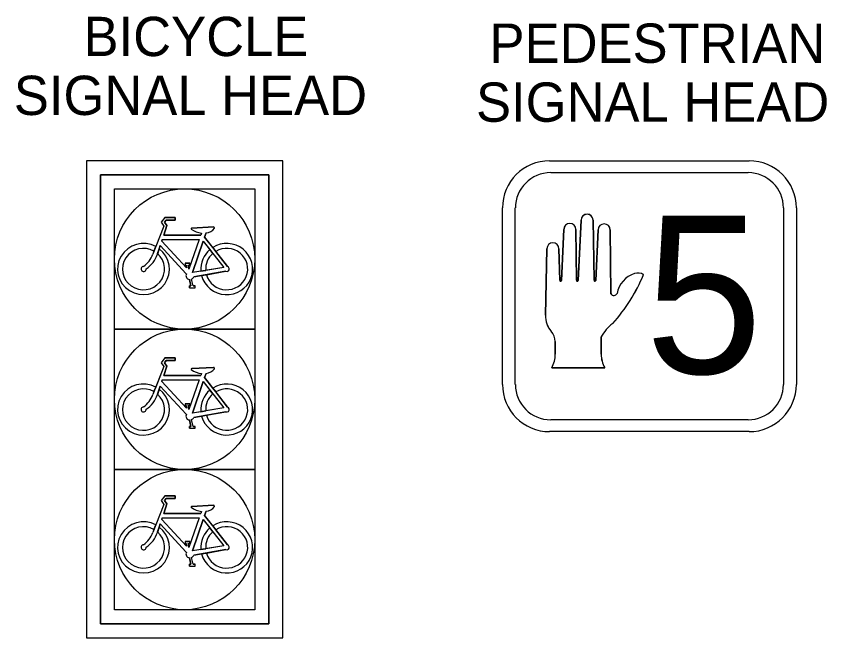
# Model space of a CAD drawing. Extents: x -30.3 to 21.6, y 6.6 to 27.2.
# Drawn here: x 18.672 to 21.56, y 9.341 to 11.556 of the extents above; entities that cross this region are included whole.
import ezdxf

# ---------------------------------------------------------------- set-up
doc = ezdxf.new("R2010")
doc.units = 0
for name, color, linetype in [('Default', 7, 'Continuous'), ('UT_X_Water', 7, 'Continuous'), ('VG_X_Cells', 7, 'Continuous')]:
    doc.layers.add(name, color=color, linetype=linetype)

# ---------------------------------------------------------------- blocks, each defined once
blk = doc.blocks.new('HAND')
at = {"layer": 'Default'}
for points in [[(0.00046, 0.10474), (0.00044, 0.10454), (0.00404, 0.17759), (0.00405, 0.17759)], [(0.01857, 0.17759), (0.01856, 0.17759), (0.01992, 0.10497), (0.01992, 0.10496)], [(-0.01964, 0.10473), (-0.01966, 0.10454), (-0.0167, 0.16646), (-0.0167, 0.16646)], [(-0.00218, 0.16646), (-0.0022, 0.16646), (-0.0014, 0.10497), (-0.0014, 0.10497)], [(0.02178, 0.10473), (0.02176, 0.10454), (0.0247, 0.16586), (0.0247, 0.16586)], [(0.03922, 0.16586), (0.03922, 0.16586), (0.04024, 0.08875), (0.04024, 0.08875)], [(-0.03873, 0.06259), (-0.03874, 0.06259), (-0.03723, 0.143), (-0.03723, 0.143)], [(-0.02271, 0.143), (-0.02273, 0.143), (-0.0215, 0.10497), (-0.0215, 0.10497)], [(0.04768, 0.08902), (0.04767, 0.08901)], [(-0.03203, 0.04323), (-0.03205, 0.04321)], [(-0.02709, 0.01543), (-0.02709, 0.01543), (-0.02709, 0.03084), (-0.02709, 0.03084)], [(0.02843, 0.03645), (0.02843, 0.03645), (0.02843, 0.01543), (0.02843, 0.01543)], [(0.03266, -0.00083), (-0.03133, -0.00083), (-0.03132, -0.00082)], [(0.03266, -0.00082), (0.03266, -0.00083)]]:
    blk.add_lwpolyline(points, dxfattribs=at)
for centre, radius, start, end in [((0.01131, 0.17759), 0.00726, 0, 180), ((-0.00944, 0.16646), 0.00726, 0, 180), ((0.03196, 0.16586), 0.00726, 0, 180), ((-0.02997, 0.143), 0.00726, 0, 180), ((-0.11405, 0.19246), 0.20979, 318.20581, 337.37116), ((0.07799, 0.0836), 0.0308, 107.24664, 169.88264), ((0.07298, 0.10185), 0.01189, 56.22904, 110.27261), ((-0.02058, 0.10476), 0.000943, 167.14009, 358.60988), ((-0.00048, 0.10476), 0.000943, 167.14009, 358.60988), ((0.02084, 0.10475), 0.000943, 167.14009, 358.60988), ((0.0439, 0.0907), 0.00414, 208.07031, 335.99597), ((-0.01095, 0.06133), 0.02781, 177.39642, 220.65739), ((0.07421, 0.01116), 0.05231, 127.51943, 151.0809), ((-0.04757, 0.02985), 0.02051, 2.77491, 40.72121), ((-0.0593, 0.01514), 0.03221, 330.28872, 0.51813), ((0.06064, 0.01514), 0.03221, 179.48187, 209.71128)]:
    blk.add_arc(centre, radius, start, end, dxfattribs=at)

msp = doc.modelspace()

# ---------------------------------------------------------------- linework, layer by layer
at = {"layer": 'VG_X_Cells'}
for p, q in [((20.5725, 11.041), (21.2834, 11.041)), ((20.5761, 10.9988), (21.2798, 10.9988)), ((20.4043, 10.2439), (20.4043, 10.8728)), ((20.4501, 10.2439), (20.4501, 10.8728)), ((21.4058, 10.8728), (21.4058, 10.2439)), ((21.4516, 10.8728), (21.4516, 10.2439)), ((19.2013, 10.8391), (19.1883, 10.8221)), ((19.2013, 10.8391), (19.2386, 10.8391)), ((19.2386, 10.8391), (19.2386, 10.8297)), ((19.1978, 10.8083), (19.1583, 10.7084)), ((19.1883, 10.8221), (19.1978, 10.8083)), ((19.2083, 10.8098), (19.1971, 10.776)), ((19.2061, 10.8297), (19.2001, 10.8218)), ((19.2001, 10.8218), (19.2083, 10.8098)), ((19.2386, 10.8297), (19.2061, 10.8297)), ((19.2061, 10.8297), (19.2061, 10.8297)), ((19.2971, 10.801), (19.3752, 10.8051)), ((19.1971, 10.776), (19.3291, 10.776)), ((19.3317, 10.7835), (19.3291, 10.776)), ((19.3483, 10.7842), (19.343, 10.7687)), ((19.192, 10.7606), (19.19, 10.7548)), ((19.19, 10.7548), (19.2782, 10.6595)), ((19.192, 10.7606), (19.3236, 10.7606)), ((19.3236, 10.7606), (19.2864, 10.6552)), ((19.3382, 10.7547), (19.2999, 10.6427)), ((19.3382, 10.7547), (19.4115, 10.6606)), ((19.343, 10.7687), (19.4246, 10.6639)), ((19.1848, 10.739), (19.1746, 10.7084)), ((19.1848, 10.739), (19.2778, 10.6383)), ((19.2734, 10.6759), (19.2897, 10.6759)), ((19.2734, 10.6759), (19.2734, 10.669)), ((19.2734, 10.669), (19.2769, 10.669)), ((19.2769, 10.669), (19.2782, 10.6595)), ((19.2846, 10.669), (19.2864, 10.6552)), ((19.2846, 10.669), (19.2897, 10.669)), ((19.2897, 10.6759), (19.2897, 10.669)), ((19.4115, 10.6606), (19.2999, 10.6427)), ((19.4188, 10.6471), (19.3041, 10.6271)), ((19.2943, 10.595), (19.2889, 10.6179)), ((19.3024, 10.595), (19.2968, 10.6192)), ((19.2891, 10.5881), (19.2891, 10.595)), ((19.2891, 10.595), (19.2943, 10.595)), ((19.2891, 10.5881), (19.3091, 10.5881)), ((19.3024, 10.595), (19.3091, 10.595)), ((19.3091, 10.5881), (19.3091, 10.595)), ((19.2013, 10.3385), (19.1883, 10.3214)), ((19.1883, 10.3214), (19.1978, 10.3076)), ((19.2061, 10.329), (19.2001, 10.3211)), ((19.2001, 10.3211), (19.2083, 10.3091)), ((19.2013, 10.3385), (19.2386, 10.3385)), ((19.2386, 10.329), (19.2061, 10.329)), ((19.2061, 10.329), (19.2061, 10.329)), ((19.2386, 10.3385), (19.2386, 10.329)), ((19.1978, 10.3076), (19.1583, 10.2077)), ((19.2083, 10.3091), (19.1971, 10.2754)), ((19.2971, 10.3004), (19.3752, 10.3045)), ((19.3317, 10.2829), (19.3291, 10.2754)), ((19.3483, 10.2835), (19.343, 10.2681)), ((19.192, 10.26), (19.19, 10.2542)), ((19.19, 10.2542), (19.2782, 10.1588)), ((19.192, 10.26), (19.3236, 10.26)), ((19.1971, 10.2754), (19.3291, 10.2754)), ((19.3236, 10.26), (19.2864, 10.1546)), ((19.3382, 10.254), (19.2999, 10.1421)), ((19.3382, 10.254), (19.4115, 10.16)), ((19.343, 10.2681), (19.4246, 10.1633)), ((19.1848, 10.2383), (19.1746, 10.2077)), ((19.1848, 10.2383), (19.2778, 10.1376)), ((19.2734, 10.1752), (19.2897, 10.1752)), ((19.2734, 10.1752), (19.2734, 10.1684)), ((19.2734, 10.1684), (19.2769, 10.1684)), ((19.2769, 10.1684), (19.2782, 10.1588)), ((19.2846, 10.1684), (19.2864, 10.1546)), ((19.2846, 10.1684), (19.2897, 10.1684)), ((19.2897, 10.1752), (19.2897, 10.1684)), ((19.4115, 10.16), (19.2999, 10.1421)), ((19.4188, 10.1464), (19.3041, 10.1265)), ((19.2943, 10.0943), (19.2889, 10.1173)), ((19.3024, 10.0943), (19.2968, 10.1185)), ((21.2798, 10.118), (20.5761, 10.118)), ((19.2891, 10.0875), (19.2891, 10.0943)), ((19.2891, 10.0943), (19.2943, 10.0943)), ((19.2891, 10.0875), (19.3091, 10.0875)), ((19.3024, 10.0943), (19.3091, 10.0943)), ((19.3091, 10.0875), (19.3091, 10.0943)), ((21.2834, 10.0757), (20.5725, 10.0757)), ((19.2013, 9.8472), (19.1883, 9.8302)), ((19.1883, 9.8302), (19.1978, 9.8163)), ((19.2061, 9.8377), (19.2001, 9.8298)), ((19.2001, 9.8298), (19.2083, 9.8179)), ((19.2013, 9.8472), (19.2386, 9.8472)), ((19.2386, 9.8377), (19.2061, 9.8377)), ((19.2061, 9.8377), (19.2061, 9.8377)), ((19.2386, 9.8472), (19.2386, 9.8377)), ((19.1978, 9.8163), (19.1583, 9.7165)), ((19.2083, 9.8179), (19.1971, 9.7841)), ((19.2971, 9.8091), (19.3752, 9.8132)), ((19.3483, 9.7922), (19.343, 9.7768)), ((19.192, 9.7687), (19.19, 9.7629)), ((19.19, 9.7629), (19.2782, 9.6675)), ((19.192, 9.7687), (19.3236, 9.7687)), ((19.1971, 9.7841), (19.3291, 9.7841)), ((19.3236, 9.7687), (19.2864, 9.6633)), ((19.3317, 9.7916), (19.3291, 9.7841)), ((19.343, 9.7768), (19.4246, 9.672)), ((19.1848, 9.747), (19.1746, 9.7165)), ((19.1848, 9.747), (19.2778, 9.6464)), ((19.3382, 9.7628), (19.2999, 9.6508)), ((19.3382, 9.7628), (19.4115, 9.6687)), ((19.2734, 9.684), (19.2897, 9.684)), ((19.2734, 9.684), (19.2734, 9.6771)), ((19.2734, 9.6771), (19.2769, 9.6771)), ((19.2769, 9.6771), (19.2782, 9.6675)), ((19.2846, 9.6771), (19.2864, 9.6633)), ((19.2846, 9.6771), (19.2897, 9.6771)), ((19.2897, 9.684), (19.2897, 9.6771)), ((19.4115, 9.6687), (19.2999, 9.6508)), ((19.4188, 9.6552), (19.3041, 9.6352)), ((19.2943, 9.6031), (19.2889, 9.626)), ((19.3024, 9.6031), (19.2968, 9.6273)), ((19.2891, 9.5962), (19.2891, 9.6031)), ((19.2891, 9.6031), (19.2943, 9.6031)), ((19.2891, 9.5962), (19.3091, 9.5962)), ((19.3024, 9.6031), (19.3091, 9.6031)), ((19.3091, 9.5962), (19.3091, 9.6031))]:
    msp.add_line(p, q, dxfattribs=at)
for points in [[(18.9216, 9.341), (19.6216, 9.341), (19.6216, 11.041), (18.9216, 11.041)], [(18.9716, 9.391), (19.5716, 9.391), (19.5716, 10.991), (18.9716, 10.991)], [(18.9716, 10.991), (19.5716, 10.991), (19.5716, 9.391), (18.9716, 9.391)], [(19.0216, 10.941), (19.5216, 10.941), (19.5216, 9.441), (19.0216, 9.441)], [(19.0216, 10.941), (19.5216, 10.941), (19.5216, 10.441), (19.0216, 10.441)], [(19.0216, 10.441), (19.5216, 10.441), (19.5216, 9.941), (19.0216, 9.941)], [(19.0216, 9.941), (19.5216, 9.941), (19.5216, 9.441), (19.0216, 9.441)]]:
    msp.add_lwpolyline(points, close=True, dxfattribs=at)
for points in [[(19.3317, 10.7835), (19.3291, 10.776), (19.1971, 10.776), (19.2083, 10.8098), (19.2001, 10.8218), (19.2061, 10.8297), (19.2386, 10.8297), (19.2386, 10.8391), (19.2013, 10.8391), (19.1883, 10.8221), (19.1978, 10.8083), (19.1689, 10.7352), (19.1625, 10.7191), (19.1583, 10.7084)], [(19.3752, 10.8051), (19.2971, 10.801)], [(20.6843, 10.8293), (20.6737, 10.6145), (20.6737, 10.6145)], [(20.7311, 10.6152), (20.7271, 10.8293)], [(19.4246, 10.6639), (19.3824, 10.7181), (19.3718, 10.7317), (19.343, 10.7687), (19.3483, 10.7842)], [(20.6231, 10.7964), (20.6144, 10.6145), (20.6145, 10.6145)], [(20.6682, 10.6152), (20.6659, 10.7964), (20.6659, 10.7964)], [(20.7452, 10.7947), (20.7365, 10.6145), (20.7365, 10.6145)], [(20.791, 10.5674), (20.788, 10.7947)], [(19.3236, 10.7606), (19.2864, 10.6552), (19.2846, 10.669), (19.2897, 10.669), (19.2897, 10.6759), (19.2734, 10.6759), (19.2734, 10.669), (19.2769, 10.669), (19.2782, 10.6595), (19.19, 10.7548), (19.192, 10.7606), (19.3236, 10.7606)], [(19.3724, 10.7108), (19.4115, 10.6606), (19.3468, 10.6502), (19.3296, 10.6475), (19.2999, 10.6427), (19.3382, 10.7547), (19.3618, 10.7244), (19.3724, 10.7108)], [(19.1625, 10.7191), (19.1689, 10.7352)], [(19.1752, 10.7101), (19.181, 10.7276), (19.1848, 10.739), (19.2778, 10.6383)], [(19.181, 10.7276), (19.1752, 10.7101)], [(19.3724, 10.7108), (19.3618, 10.7244)], [(19.3718, 10.7317), (19.3824, 10.7181)], [(20.5626, 10.7273), (20.5582, 10.4903)], [(20.609, 10.6152), (20.6053, 10.7273), (20.6054, 10.7273)], [(19.1746, 10.7084), (19.1752, 10.7101)], [(19.3041, 10.6271), (19.3322, 10.632), (19.3495, 10.635), (19.4188, 10.6471)], [(19.3296, 10.6475), (19.3468, 10.6502)], [(19.3495, 10.635), (19.3322, 10.632)], [(19.2889, 10.6179), (19.2943, 10.595), (19.2891, 10.595), (19.2891, 10.5881), (19.3091, 10.5881), (19.3091, 10.595), (19.3024, 10.595), (19.2968, 10.6192)], [(20.6144, 10.614), (20.6144, 10.6139), (20.6144, 10.6139)], [(20.6737, 10.6142), (20.6737, 10.6139), (20.6736, 10.614)], [(20.7365, 10.6141), (20.7365, 10.6139), (20.7365, 10.6139)], [(20.8129, 10.5682), (20.8129, 10.5682)], [(20.5779, 10.4332), (20.5779, 10.4332)], [(20.7561, 10.3513), (20.7561, 10.4132)], [(20.5925, 10.3967), (20.5925, 10.3513)], [(19.3317, 10.2829), (19.3291, 10.2754), (19.1971, 10.2754), (19.2083, 10.3091), (19.2001, 10.3211), (19.2061, 10.329), (19.2386, 10.329), (19.2386, 10.3385), (19.2013, 10.3385), (19.1883, 10.3214), (19.1978, 10.3076), (19.1689, 10.2346), (19.1625, 10.2184), (19.1583, 10.2077)], [(19.3752, 10.3045), (19.2971, 10.3004)], [(19.4246, 10.1633), (19.3824, 10.2174), (19.3718, 10.2311), (19.343, 10.2681), (19.3483, 10.2835)], [(20.58, 10.3034), (20.7686, 10.3034)], [(19.3236, 10.26), (19.2864, 10.1546), (19.2846, 10.1684), (19.2897, 10.1684), (19.2897, 10.1752), (19.2734, 10.1752), (19.2734, 10.1684), (19.2769, 10.1684), (19.2782, 10.1588), (19.19, 10.2542), (19.192, 10.26), (19.3236, 10.26)], [(19.3724, 10.2101), (19.4115, 10.16), (19.3468, 10.1496), (19.3296, 10.1468), (19.2999, 10.1421), (19.3382, 10.254), (19.3618, 10.2238), (19.3724, 10.2101)], [(19.1625, 10.2184), (19.1689, 10.2346)], [(19.1752, 10.2094), (19.181, 10.2269), (19.1848, 10.2383), (19.2778, 10.1376)], [(19.181, 10.2269), (19.1752, 10.2094)], [(19.3718, 10.2311), (19.3824, 10.2174)], [(19.1746, 10.2077), (19.1752, 10.2094)], [(19.3724, 10.2101), (19.3618, 10.2238)], [(19.3041, 10.1265), (19.3322, 10.1314), (19.3495, 10.1344), (19.4188, 10.1464)], [(19.3296, 10.1468), (19.3468, 10.1496)], [(19.2889, 10.1173), (19.2943, 10.0943), (19.2891, 10.0943), (19.2891, 10.0875), (19.3091, 10.0875), (19.3091, 10.0943), (19.3024, 10.0943), (19.2968, 10.1185)], [(19.3495, 10.1344), (19.3322, 10.1314)], [(19.3317, 9.7916), (19.3291, 9.7841), (19.1971, 9.7841), (19.2083, 9.8179), (19.2001, 9.8298), (19.2061, 9.8377), (19.2386, 9.8377), (19.2386, 9.8472), (19.2013, 9.8472), (19.1883, 9.8302), (19.1978, 9.8163), (19.1689, 9.7433), (19.1625, 9.7272), (19.1583, 9.7165)], [(19.3752, 9.8132), (19.2971, 9.8091)], [(19.4246, 9.672), (19.3824, 9.7261), (19.3718, 9.7398), (19.343, 9.7768), (19.3483, 9.7922)], [(19.3236, 9.7687), (19.2864, 9.6633), (19.2846, 9.6771), (19.2897, 9.6771), (19.2897, 9.684), (19.2734, 9.684), (19.2734, 9.6771), (19.2769, 9.6771), (19.2782, 9.6675), (19.19, 9.7629), (19.192, 9.7687), (19.3236, 9.7687)], [(19.1625, 9.7272), (19.1689, 9.7433)], [(19.1752, 9.7181), (19.181, 9.7356), (19.1848, 9.747), (19.2778, 9.6464)], [(19.181, 9.7356), (19.1752, 9.7181)], [(19.3724, 9.7189), (19.4115, 9.6687), (19.3468, 9.6583), (19.3296, 9.6555), (19.2999, 9.6508), (19.3382, 9.7628), (19.3618, 9.7325), (19.3724, 9.7189)], [(19.3718, 9.7398), (19.3824, 9.7261)], [(19.1746, 9.7165), (19.1752, 9.7181)], [(19.3724, 9.7189), (19.3618, 9.7325)], [(19.3041, 9.6352), (19.3322, 9.6401), (19.3495, 9.6431), (19.4188, 9.6552)], [(19.3296, 9.6555), (19.3468, 9.6583)], [(19.2889, 9.626), (19.2943, 9.6031), (19.2891, 9.6031), (19.2891, 9.5962), (19.3091, 9.5962), (19.3091, 9.6031), (19.3024, 9.6031), (19.2968, 9.6273)], [(19.3495, 9.6431), (19.3322, 9.6401)]]:
    msp.add_lwpolyline(points, dxfattribs=at)
for centre in [(19.2716, 10.691), (19.2716, 10.191), (19.2716, 9.691)]:
    msp.add_circle(centre, 0.25, dxfattribs=at)
for centre, radius, start, end in [((20.5725, 10.8728), 0.1682, 90, 180), ((21.2834, 10.8728), 0.1682, 360, 90), ((20.5761, 10.8728), 0.1259, 90, 180), ((21.2798, 10.8728), 0.1259, 360, 90), ((20.7057, 10.8293), 0.0214, 360, 180), ((20.6445, 10.7964), 0.0214, 0, 180), ((20.7666, 10.7947), 0.0214, 0, 180), ((20.584, 10.7273), 0.0214, 0, 180), ((20.3362, 10.8731), 0.6184, 318.2058, 337.3712), ((20.9022, 10.5522), 0.0908, 107.2466, 169.8826), ((20.8875, 10.606), 0.0351, 56.229, 110.2726), ((20.6117, 10.6146), 0.00278, 167.1401, 346.8691), ((20.6117, 10.6146), 0.00278, 347.3062, 358.6099), ((20.6709, 10.6146), 0.00278, 167.1401, 346.5951), ((20.6709, 10.6146), 0.00278, 351.0095, 358.6099), ((20.7338, 10.6146), 0.00278, 167.1401, 347.1404), ((20.7338, 10.6146), 0.00278, 349.4624, 358.6099), ((20.8017, 10.5732), 0.0122, 208.0703, 335.996), ((20.6401, 10.4866), 0.082, 177.3964, 220.6574), ((20.8911, 10.3387), 0.1542, 127.5194, 151.0809), ((20.5321, 10.3938), 0.0604, 2.7749, 40.7212), ((20.4976, 10.3504), 0.0949, 330.2887, 0.5181), ((20.8511, 10.3504), 0.0949, 179.4819, 209.7113), ((20.5725, 10.2439), 0.1682, 180, 270), ((20.5761, 10.2439), 0.1259, 180, 270), ((21.2798, 10.2439), 0.1259, 270, 360), ((21.2834, 10.2439), 0.1682, 270, 360)]:
    msp.add_arc(centre, radius, start, end, dxfattribs=at)
for centre, major_axis, start_param, end_param in [((19.3745, 10.8019), (-0.00335, 0), 2.773971, 4.511296), ((19.3745, 10.8019), (-0.00335, 0), 2.773971, 4.511296), ((19.297, 10.799), (-0.0021, 0), 4.638592, 6.875307), ((19.297, 10.799), (-0.0021, 0), 4.638592, 6.875307), ((19.3359, 10.8462), (0.0637, 0), 4.021161, 4.647453), ((19.3359, 10.8462), (0.0637, 0), 4.021161, 4.647453), ((19.3451, 10.8233), (0.0398, 0), 4.792509, 5.670671), ((19.3451, 10.8233), (0.0398, 0), 4.792509, 5.670671), ((19.1251, 10.6551), (0.0924, 0), 1.076976, 7.204563), ((19.1251, 10.6551), (0.0924, 0), 1.076976, 7.204563), ((19.4216, 10.6551), (0.0924, 0), 3.397571, 8.423389), ((19.4216, 10.6551), (0.0924, 0), 3.397571, 8.423389), ((19.1251, 10.6551), (0.0749, 0), 1.048306, 7.122994), ((19.1251, 10.6551), (0.0749, 0), 1.048306, 7.122994), ((19.4216, 10.6551), (0.0924, 0), 2.275408, 3.225335), ((19.4216, 10.6551), (0.0924, 0), 2.275408, 3.225335), ((19.4216, 10.6551), (0.0749, 0), 3.41651, 8.40353), ((19.4216, 10.6551), (0.0749, 0), 3.41651, 8.40353), ((19.0698, 10.7391), (0.0938, 0), 5.341101, 5.944471), ((19.0698, 10.7391), (0.0938, 0), 5.341101, 5.944471), ((19.0848, 10.7347), (0.0937, 0), 5.2704, 5.993881), ((19.0848, 10.7347), (0.0937, 0), 5.2704, 5.993881), ((19.4216, 10.6551), (0.0749, 0), 2.287038, 3.207235), ((19.4216, 10.6551), (0.0749, 0), 2.287038, 3.207235), ((19.1254, 10.6554), (0.00902, 0), 1.620706, 6.390526), ((19.1254, 10.6554), (0.00902, 0), 1.620706, 6.390526), ((19.4219, 10.6554), (0.00902, 0), 4.360591, 7.547737), ((19.4219, 10.6554), (0.00902, 0), 4.360591, 7.547737), ((19.2906, 10.632), (0.0143, 0), 2.676233, 4.593866), ((19.2906, 10.632), (0.0143, 0), 2.676233, 4.593866), ((19.2906, 10.632), (0.0143, 0), 5.15565, 5.934845), ((19.2906, 10.632), (0.0143, 0), 5.15565, 5.934845), ((19.297, 10.2983), (-0.0021, 0), 4.638592, 6.875307), ((19.297, 10.2983), (-0.0021, 0), 4.638592, 6.875307), ((19.3359, 10.3456), (0.0637, 0), 4.021161, 4.647453), ((19.3359, 10.3456), (0.0637, 0), 4.021161, 4.647453), ((19.3451, 10.3226), (0.0398, 0), 4.792509, 5.670671), ((19.3451, 10.3226), (0.0398, 0), 4.792509, 5.670671), ((19.3745, 10.3012), (-0.00335, 0), 2.773971, 4.511296), ((19.3745, 10.3012), (-0.00335, 0), 2.773971, 4.511296), ((19.1251, 10.1544), (0.0924, 0), 1.076976, 7.204563), ((19.1251, 10.1544), (0.0924, 0), 1.076976, 7.204563), ((19.1251, 10.1544), (0.0749, 0), 1.048306, 7.122994), ((19.1251, 10.1544), (0.0749, 0), 1.048306, 7.122994), ((19.4216, 10.1544), (0.0924, 0), 3.397571, 8.423389), ((19.4216, 10.1544), (0.0924, 0), 3.397571, 8.423389), ((19.4216, 10.1544), (0.0749, 0), 3.41651, 8.40353), ((19.4216, 10.1544), (0.0749, 0), 3.41651, 8.40353), ((19.0698, 10.2385), (0.0938, 0), 5.341101, 5.944471), ((19.0698, 10.2385), (0.0938, 0), 5.341101, 5.944471), ((19.0848, 10.2341), (0.0937, 0), 5.2704, 5.993881), ((19.0848, 10.2341), (0.0937, 0), 5.2704, 5.993881), ((19.4216, 10.1544), (0.0924, 0), 2.275408, 3.225335), ((19.4216, 10.1544), (0.0924, 0), 2.275408, 3.225335), ((19.4216, 10.1544), (0.0749, 0), 2.287038, 3.207235), ((19.4216, 10.1544), (0.0749, 0), 2.287038, 3.207235), ((19.1254, 10.1548), (0.00902, 0), 1.620706, 6.390526), ((19.1254, 10.1548), (0.00902, 0), 1.620706, 6.390526), ((19.4219, 10.1548), (0.00902, 0), 4.360591, 7.547737), ((19.4219, 10.1548), (0.00902, 0), 4.360591, 7.547737), ((19.2906, 10.1313), (0.0143, 0), 2.676233, 4.593866), ((19.2906, 10.1313), (0.0143, 0), 2.676233, 4.593866), ((19.2906, 10.1313), (0.0143, 0), 5.15565, 5.934845), ((19.2906, 10.1313), (0.0143, 0), 5.15565, 5.934845), ((19.297, 9.807), (-0.0021, 0), 4.638592, 6.875307), ((19.297, 9.807), (-0.0021, 0), 4.638592, 6.875307), ((19.3359, 9.8543), (0.0637, 0), 4.021161, 4.647453), ((19.3359, 9.8543), (0.0637, 0), 4.021161, 4.647453), ((19.3451, 9.8313), (0.0398, 0), 4.792509, 5.670671), ((19.3451, 9.8313), (0.0398, 0), 4.792509, 5.670671), ((19.3745, 9.81), (-0.00335, 0), 2.773971, 4.511296), ((19.3745, 9.81), (-0.00335, 0), 2.773971, 4.511296), ((19.1251, 9.6631), (0.0924, 0), 1.076976, 7.204563), ((19.1251, 9.6631), (0.0924, 0), 1.076976, 7.204563), ((19.1251, 9.6631), (0.0749, 0), 1.048306, 7.122994), ((19.1251, 9.6631), (0.0749, 0), 1.048306, 7.122994), ((19.4216, 9.6631), (0.0924, 0), 3.397571, 8.423389), ((19.4216, 9.6631), (0.0924, 0), 3.397571, 8.423389), ((19.4216, 9.6631), (0.0749, 0), 3.41651, 8.40353), ((19.4216, 9.6631), (0.0749, 0), 3.41651, 8.40353), ((19.0698, 9.7472), (0.0938, 0), 5.341101, 5.944471), ((19.0698, 9.7472), (0.0938, 0), 5.341101, 5.944471), ((19.0848, 9.7428), (0.0937, 0), 5.2704, 5.993881), ((19.0848, 9.7428), (0.0937, 0), 5.2704, 5.993881), ((19.4216, 9.6631), (0.0924, 0), 2.275408, 3.225335), ((19.4216, 9.6631), (0.0924, 0), 2.275408, 3.225335), ((19.4216, 9.6631), (0.0749, 0), 2.287038, 3.207235), ((19.4216, 9.6631), (0.0749, 0), 2.287038, 3.207235), ((19.1254, 9.6635), (0.00902, 0), 1.620706, 6.390526), ((19.1254, 9.6635), (0.00902, 0), 1.620706, 6.390526), ((19.4219, 9.6635), (0.00902, 0), 4.360591, 7.547737), ((19.4219, 9.6635), (0.00902, 0), 4.360591, 7.547737), ((19.2906, 9.64), (0.0143, 0), 2.676233, 4.593866), ((19.2906, 9.64), (0.0143, 0), 2.676233, 4.593866), ((19.2906, 9.64), (0.0143, 0), 5.15565, 5.934845), ((19.2906, 9.64), (0.0143, 0), 5.15565, 5.934845)]:
    msp.add_ellipse(centre, major_axis=major_axis, ratio=0.985514, start_param=start_param, end_param=end_param, dxfattribs=at)

# ---------------------------------------------------------------- block references
at = {"layer": 'VG_X_Cells', "xscale": 2.9475828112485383, "yscale": 2.947582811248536, "rotation": -4.10307326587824e-09}
msp.add_blockref('HAND', (20.6723, 10.3058), dxfattribs=at)

# ---------------------------------------------------------------- texts
at = {"layer": 'UT_X_Water'}
for s, p in [('BICYCLE', (18.9115, 11.4142)), ('PEDESTRIAN', (20.3581, 11.3901)), ('SIGNAL HEAD', (18.6631, 11.2042)), ('SIGNAL HEAD', (20.3101, 11.1801))]:
    msp.add_text(s, height=0.14, dxfattribs=at).set_placement(p)
at = {"layer": 'VG_X_Cells'}
msp.add_text('5', height=0.5625, dxfattribs=at).set_placement((20.9125, 10.2826))

doc.saveas('drawing.dxf')
